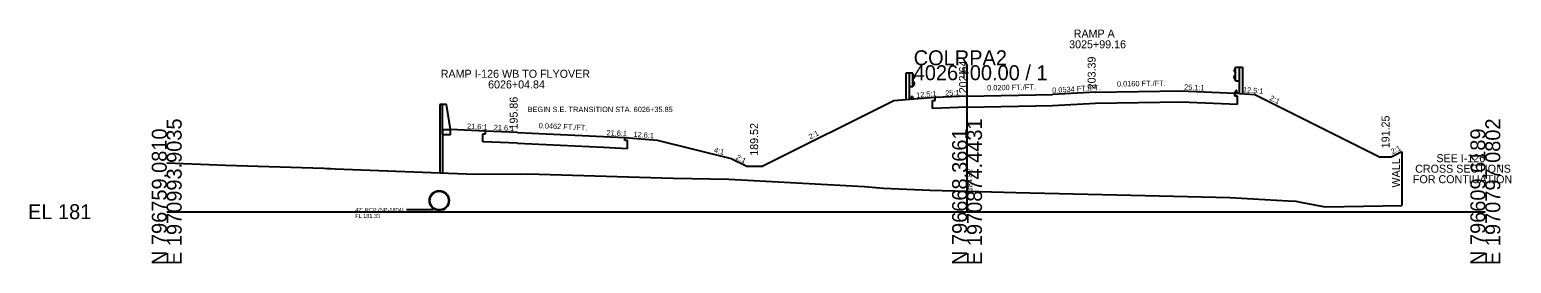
# Model space of a CAD drawing. Extents: x -26 to 1971083, y -10 to 798159.
# Drawn here: x 1170 to 1447.7, y 1990.3 to 2034.1 of the extents above; entities that cross this region are included whole.
import ezdxf

# ---------------------------------------------------------------- set-up
doc = ezdxf.new("R2010")
doc.units = 0
for name, color, linetype in [('RD_GPK_XS_Cell', 7, 'Continuous'), ('RD_XS_Base', 7, 'Continuous'), ('RD_XS_Box', 7, 'Continuous'), ('RD_XS_CurbTop', 7, 'Continuous'), ('RD_XS_EarthShd', 7, 'Continuous'), ('RD_XS_ExGround', 7, 'Continuous'), ('RD_XS_GR', 7, 'Continuous'), ('RD_XS_MedBWall', 7, 'Continuous'), ('RD_XS_Pave', 7, 'Continuous'), ('RD_XS_PaveShd', 7, 'Continuous'), ('RD_XS_Pipe', 7, 'Continuous'), ('RD_XS_TieSlope', 7, 'Continuous'), ('RD_XS_TX_Elev_EX', 7, 'Continuous'), ('RD_XS_TX_Elev_PR', 7, 'Continuous'), ('RD_XS_TX_Misc', 7, 'Continuous'), ('RD_XS_TX_Notes', 7, 'Continuous'), ('RD_XS_TX_ShdSlope', 7, 'Continuous'), ('RD_XS_TX_Slope', 7, 'Continuous'), ('RD_XS_TX_Station', 7, 'Continuous')]:
    doc.layers.add(name, color=color, linetype=linetype)

msp = doc.modelspace()

# ---------------------------------------------------------------- linework, layer by layer
at = {"layer": 'RD_GPK_XS_Cell'}
for p, q in [((1345.69, 2000), (1345.69, 2027.46)), ((1195.69, 2000), (1345.69, 2000)), ((1345.69, 2000), (1442.83, 2000))]:
    msp.add_line(p, q, dxfattribs=at)
at = {"layer": 'RD_XS_Base'}
for p, q in [((1395.85, 2021.69), (1395.85, 2022.25)), ((1339.19, 2020.82), (1339.69, 2020.84)), ((1339.19, 2019.34), (1339.19, 2020.82)), ((1345.69, 2019.6), (1339.19, 2019.34)), ((1339.69, 2020.84), (1339.69, 2021.4)), ((1345.69, 2019.6), (1361.69, 2019.92)), ((1361.69, 2019.92), (1369.79, 2020.35)), ((1369.79, 2020.35), (1385.83, 2020.61)), ((1385.83, 2020.61), (1396.35, 2020.19)), ((1396.35, 2021.67), (1395.85, 2021.69)), ((1396.35, 2020.19), (1396.35, 2021.67)), ((1254.92, 2014.6), (1255.42, 2014.57)), ((1254.92, 2013.12), (1254.92, 2014.6)), ((1255.42, 2014.57), (1255.42, 2015.13)), ((1281.58, 2013.36), (1281.58, 2013.92)), ((1261.46, 2012.82), (1254.92, 2013.12)), ((1261.46, 2012.82), (1277.55, 2012.07)), ((1277.55, 2012.07), (1282.08, 2011.86)), ((1282.08, 2013.34), (1281.58, 2013.36)), ((1282.08, 2011.86), (1282.08, 2013.34))]:
    msp.add_line(p, q, dxfattribs=at)
at = {"layer": 'RD_XS_Box'}
for p, q in [((1247.35, 2020.1), (1246.85, 2020.1)), ((1246.85, 2020.1), (1246.85, 2007.3)), ((1247.35, 2015.47), (1247.35, 2007.28))]:
    msp.add_line(p, q, dxfattribs=at)
at = {"layer": 'RD_XS_CurbTop'}
for p, q in [((1395.85, 2022.25), (1396.1, 2022.71)), ((1395.85, 2022.25), (1396.32, 2022.21)), ((1396.32, 2022.21), (1396.26, 2022.65)), ((1335.22, 2021.04), (1335.28, 2021.48)), ((1335.69, 2021.08), (1335.22, 2021.04)), ((1335.69, 2021.08), (1335.44, 2021.54))]:
    msp.add_line(p, q, dxfattribs=at)
for centre, major_axis, start_param, end_param in [((1396.17, 2022.62), (0, -0.131), 1.762783, 4.036677), ((1335.37, 2021.45), (0, 0.131), 5.388101, 7.661995)]:
    msp.add_ellipse(centre, major_axis=major_axis, ratio=0.686, start_param=start_param, end_param=end_param, dxfattribs=at)
at = {"layer": 'RD_XS_EarthShd'}
for p, q in [((1339.69, 2021.4), (1335.69, 2021.08)), ((1255.42, 2015.13), (1248.85, 2015.44)), ((1281.58, 2013.92), (1287.61, 2013.44))]:
    msp.add_line(p, q, dxfattribs=at)
at = {"layer": 'RD_XS_ExGround'}
msp.add_line((1412.83, 2000.94), (1427.15, 2001.16), dxfattribs=at)
msp.add_lwpolyline([(1195.69, 2009.15), (1206.68, 2008.75), (1225.12, 2008.14), (1225.7, 2008.13), (1226.36, 2008.1), (1227.23, 2008.06), (1253.43, 2007.04), (1263.37, 2007.07), (1290.6, 2006.26), (1301.04, 2006.08), (1326.45, 2004.71), (1330.03, 2004.44), (1338.7, 2004.01), (1345.69, 2003.82), (1354.83, 2003.58), (1376.48, 2003.11), (1394.94, 2002.68), (1405.85, 2002.06), (1407.34, 2001.96), (1408.49, 2001.73), (1412.83, 2000.94)], dxfattribs=at)
at = {"layer": 'RD_XS_GR'}
for p, q in [((1334.87, 2025.95), (1334.21, 2025.95)), ((1334.21, 2025.95), (1334.21, 2020.9)), ((1335.54, 2025.95), (1334.87, 2025.95)), ((1334.87, 2025.95), (1334.87, 2021.01)), ((1335.54, 2023.39), (1335.54, 2025.95)), ((1335.54, 2025.79), (1335.81, 2025.35)), ((1335.81, 2025.24), (1335.54, 2024.8)), ((1335.81, 2025.35), (1335.81, 2025.24)), ((1396, 2026.96), (1395.73, 2026.52)), ((1395.73, 2026.52), (1395.73, 2026.41)), ((1395.73, 2026.41), (1396, 2025.97)), ((1395.73, 2025.27), (1396, 2025.71)), ((1395.73, 2025.16), (1395.73, 2025.27)), ((1396, 2024.72), (1395.73, 2025.16)), ((1396, 2027.12), (1396.67, 2027.12)), ((1396, 2024.56), (1396, 2027.12)), ((1396, 2024.56), (1396.67, 2024.56)), ((1396.67, 2027.12), (1397.34, 2027.12)), ((1396.67, 2027.12), (1396.67, 2022.18)), ((1397.34, 2027.12), (1397.34, 2022.07)), ((1335.54, 2023.39), (1334.87, 2023.39)), ((1335.81, 2024.1), (1335.54, 2024.54)), ((1335.54, 2023.55), (1335.81, 2023.99)), ((1335.81, 2023.99), (1335.81, 2024.1))]:
    msp.add_line(p, q, dxfattribs=at)
at = {"layer": 'RD_XS_MedBWall'}
for p, q in [((1248.1, 2020.1), (1247.35, 2020.1)), ((1247.35, 2014.46), (1247.35, 2020.1)), ((1248.85, 2015.44), (1248.1, 2020.1)), ((1247.35, 2015.44), (1248.85, 2015.44)), ((1248.85, 2014.44), (1247.35, 2014.44)), ((1248.85, 2014.44), (1248.85, 2015.44)), ((1427.15, 2011.25), (1427.15, 2005.11))]:
    msp.add_line(p, q, dxfattribs=at)
at = {"layer": 'RD_XS_Pave'}
for p, q in [((1345.69, 2021.64), (1361.69, 2021.96)), ((1369.79, 2022.39), (1385.83, 2022.65)), ((1261.46, 2014.86), (1277.55, 2014.11))]:
    msp.add_line(p, q, dxfattribs=at)
at = {"layer": 'RD_XS_PaveShd'}
for p, q in [((1369.79, 2022.39), (1361.69, 2021.96)), ((1385.83, 2022.65), (1395.85, 2022.25)), ((1345.69, 2021.64), (1339.69, 2021.4)), ((1261.46, 2014.86), (1255.42, 2015.13)), ((1277.55, 2014.11), (1281.58, 2013.92))]:
    msp.add_line(p, q, dxfattribs=at)
at = {"layer": 'RD_XS_Pipe'}
msp.add_line((1245.61, 2000.33), (1240.61, 2000.33), dxfattribs=at)
for radius in [1.85, 1.75]:
    msp.add_circle((1246.77, 2002.08), radius, dxfattribs=at)
at = {"layer": 'RD_XS_TieSlope'}
for p, q in [((1395.85, 2022.25), (1399.63, 2021.95)), ((1399.63, 2021.95), (1423.15, 2010.25)), ((1331.94, 2020.78), (1307.42, 2008.52)), ((1335.69, 2021.08), (1331.94, 2020.78)), ((1287.61, 2013.44), (1301.45, 2010)), ((1427.15, 2011.25), (1425.15, 2010.25)), ((1301.45, 2010), (1304.42, 2008.52)), ((1304.42, 2008.52), (1307.42, 2008.52)), ((1425.15, 2010.25), (1423.15, 2010.25)), ((1427.15, 2005.11), (1427.15, 2001.16))]:
    msp.add_line(p, q, dxfattribs=at)

# ---------------------------------------------------------------- texts
at = {"layer": 'RD_GPK_XS_Cell'}
for s, p in [('COLRPA2', (1335.69, 2027.46)), ('4026+00.00 / 1', (1335.69, 2024.66)), ('EL 181', (1169.69, 1998.6))]:
    msp.add_text(s, height=2.8, dxfattribs=at).set_placement(p)
for s, p in [('E 1970993.9035', (1198.49, 1990)), ('E 1970874.4431', (1348.49, 1990)), ('E 1970797.0802', (1445.63, 1990)), ('N 796759.0810', (1195.69, 1990)), ('N 796668.3661', (1345.69, 1990)), ('N 796609.6189', (1442.83, 1990))]:
    msp.add_text(s, height=2.8, rotation=90, dxfattribs=at).set_placement(p)
at = {"layer": 'RD_XS_Pipe'}
for s, p in [('42" RCP (NP-1804)', (1231.02, 1999.96)), ('FL 181.33', (1231.02, 1998.83))]:
    msp.add_text(s, height=0.75, dxfattribs=at).set_placement(p)
at = {"layer": 'RD_XS_TX_Elev_EX'}
msp.add_text('184.82', height=1, rotation=90, dxfattribs=at).set_placement((1346.69, 2003.82))
at = {"layer": 'RD_XS_TX_Elev_PR'}
for s, p in [(' 202.64', (1345.69, 2021.64)), (' 203.39', (1369.79, 2022.39)), (' 195.86', (1261.46, 2014.86))]:
    msp.add_text(s, height=1.5, rotation=90, dxfattribs=at).set_placement(p)
at = {"layer": 'RD_XS_TX_Misc'}
for s, p in [('189.52', (1306.53, 2010.49)), ('191.25', (1424.88, 2011.89))]:
    msp.add_text(s, height=1.5, rotation=90, dxfattribs=at).set_placement(p)
at = {"layer": 'RD_XS_TX_Notes'}
for s, height, p in [('BEGIN S.E. TRANSITION STA. 6026+35.85', 1, (1263.33, 2018.68)), ('SEE I-126', 1.5, (1433.66, 2009.28)), ('CROSS SECTIONS', 1.5, (1429.68, 2007.31)), ('FOR CONTIUATION', 1.5, (1429.26, 2005.34))]:
    msp.add_text(s, height=height, dxfattribs=at).set_placement(p)
msp.add_text('WALL', height=1.5, rotation=90, dxfattribs=at).set_placement((1426.82, 2004.53))
at = {"layer": 'RD_XS_TX_ShdSlope'}
for s, rotation, p in [('12.5:1', 4.5739, (1336.19, 2021.37)), ('12.5:1', 355.4261, (1397.37, 2022.4)), ('21.6:1', 357.3554, (1251.94, 2015.55)), ('12.6:1', 355.4533, (1283.14, 2014.05))]:
    msp.add_text(s, height=1, rotation=rotation, dxfattribs=at).set_placement(p)
at = {"layer": 'RD_XS_TX_Slope'}
for s, rotation, p in [('0.0160 FT./FT.', 0.917, (1373.8, 2023.46)), ('25:1', 2.2906, (1341.62, 2021.73)), ('0.0200 FT./FT.', 1.1458, (1349.47, 2022.72)), ('0.0534 FT./FT.', 3.558, (1361.68, 2022.26)), ('25.1:1', 357.715, (1386.36, 2022.88)), ('2:1', 333.5723, (1402.31, 2021)), ('21.6:1', 357.3554, (1256.97, 2015.31)), ('0.0462 FT./FT.', 357.3554, (1265.39, 2015.67)), ('21.6:1', 357.3554, (1278.1, 2014.33)), ('2:1', 26.5651, (1316.31, 2013.53)), ('4:1', 346.0445, (1298.18, 2011.12)), ('2:1', 333.4349, (1302.26, 2009.89)), ('2:1', 26.4277, (1425.42, 2010.74))]:
    msp.add_text(s, height=1, rotation=rotation, dxfattribs=at).set_placement(p)
at = {"layer": 'RD_XS_TX_Station'}
for s, p in [('RAMP A', (1365.68, 2032.64)), ('3025+99.16', (1364.83, 2030.64)), ('RAMP I-126 WB TO FLYOVER', (1247.05, 2025.11)), ('6026+04.84', (1255.92, 2023.11))]:
    msp.add_text(s, height=1.5, dxfattribs=at).set_placement(p)

doc.saveas('drawing.dxf')
